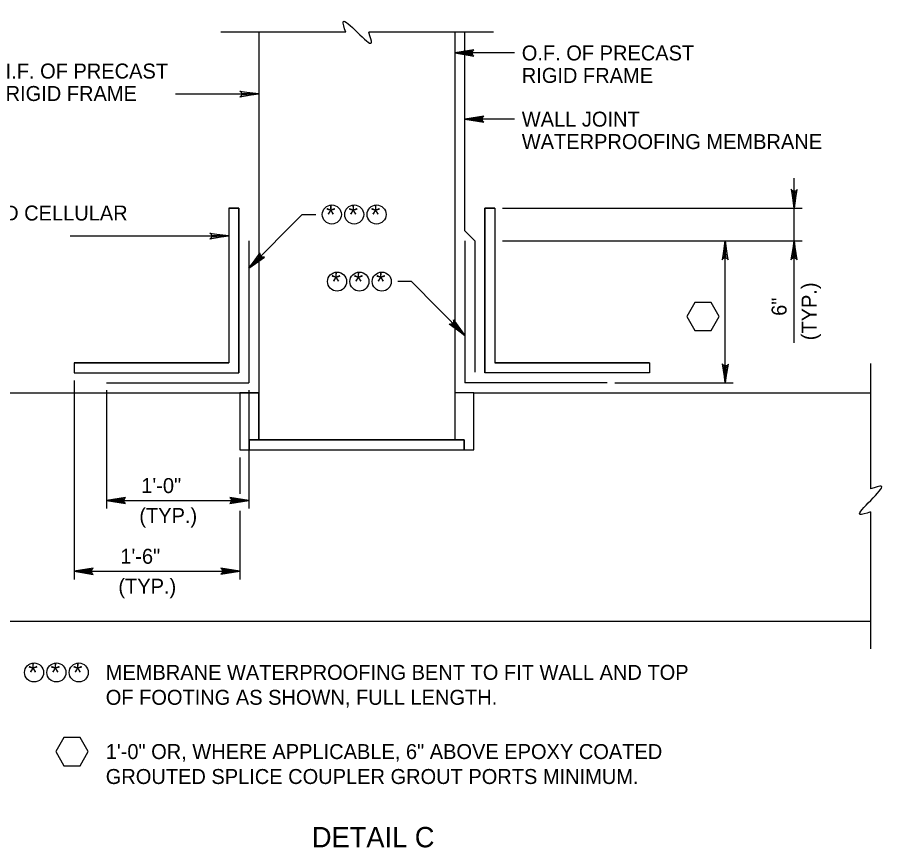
# Model space of a CAD drawing. Extents: x 641328 to 643024, y 298283 to 300065.
# Drawn here: x 641451.7 to 641625.7, y 299059.5 to 299225.9 of the extents above; entities that cross this region are included whole.
import ezdxf

# ---------------------------------------------------------------- set-up
doc = ezdxf.new("R2010")
doc.units = 0
for name, color, linetype in [('2', 7, 'Continuous'), ('Default', 7, 'Continuous'), ('S-TEXT-DIMS-N', 7, 'Continuous')]:
    doc.layers.add(name, color=color, linetype=linetype)

msp = doc.modelspace()

# ---------------------------------------------------------------- linework, layer by layer
at = {"layer": '2'}
for p, q in [((641517.5, 299222.9), (641492.5, 299222.9)), ((641500.08, 299222.9), (641500.08, 299141.21)), ((641547.13, 299222.9), (641522.13, 299222.9)), ((641539.36, 299222.9), (641539.36, 299141.21)), ((641541.36, 299183.14), (641541.36, 299222.9)), ((641543.16, 299219.37), (641539.36, 299218.78)), ((641539.36, 299218.78), (641542.97, 299219.21)), ((641542.83, 299218.95), (641539.36, 299218.78)), ((641539.36, 299218.78), (641542.83, 299218.58)), ((641542.96, 299218.32), (641539.36, 299218.78)), ((641539.36, 299218.78), (641543.15, 299218.15)), ((641539.36, 299218.78), (641542.83, 299218.77)), ((641551.33, 299218.78), (641539.36, 299218.78)), ((641542.97, 299219.21), (641542.83, 299218.95)), ((641542.83, 299218.95), (641542.83, 299218.58)), ((641542.83, 299218.58), (641542.96, 299218.32)), ((641543.15, 299218.15), (641542.96, 299218.32)), ((641542.97, 299219.21), (641543.16, 299219.37)), ((641483.37, 299210.54), (641500.08, 299210.54)), ((641496.47, 299210.97), (641496.28, 299211.13)), ((641496.28, 299211.13), (641500.08, 299210.54)), ((641500.08, 299210.54), (641496.28, 299209.9)), ((641496.28, 299209.9), (641496.48, 299210.08)), ((641496.47, 299210.97), (641496.61, 299210.7)), ((641500.08, 299210.54), (641496.47, 299210.97)), ((641496.48, 299210.08), (641500.08, 299210.54)), ((641496.61, 299210.34), (641496.48, 299210.08)), ((641496.61, 299210.7), (641500.08, 299210.54)), ((641496.61, 299210.7), (641496.61, 299210.34)), ((641500.08, 299210.54), (641496.61, 299210.34)), ((641500.08, 299210.54), (641496.61, 299210.52)), ((641545.16, 299206.1), (641541.36, 299205.51)), ((641544.97, 299205.94), (641545.16, 299206.1)), ((641541.36, 299205.51), (641544.97, 299205.94)), ((641544.83, 299205.68), (641541.36, 299205.51)), ((641541.36, 299205.51), (641544.83, 299205.32)), ((641544.96, 299205.06), (641541.36, 299205.51)), ((641541.36, 299205.51), (641545.15, 299204.88)), ((641541.36, 299205.51), (641544.83, 299205.5)), ((641551.33, 299205.51), (641541.36, 299205.51)), ((641544.97, 299205.94), (641544.83, 299205.68)), ((641544.83, 299205.68), (641544.83, 299205.32)), ((641544.83, 299205.32), (641544.96, 299205.06)), ((641545.15, 299204.88), (641544.96, 299205.06)), ((641607.34, 299160.65), (641607.34, 299193.65)), ((641606.91, 299191.25), (641606.75, 299191.44)), ((641606.75, 299191.44), (641607.34, 299187.64)), ((641606.91, 299191.25), (641607.18, 299191.11)), ((641607.34, 299187.64), (641606.91, 299191.25)), ((641607.18, 299191.11), (641607.34, 299187.64)), ((641607.18, 299191.11), (641607.54, 299191.11)), ((641607.34, 299187.64), (641607.98, 299191.43)), ((641607.8, 299191.23), (641607.34, 299187.64)), ((641607.34, 299187.64), (641607.54, 299191.11)), ((641607.34, 299187.64), (641607.36, 299191.11)), ((641607.54, 299191.11), (641607.8, 299191.23)), ((641607.98, 299191.43), (641607.8, 299191.23)), ((641494.08, 299187.64), (641494.08, 299156.64)), ((641494.08, 299187.64), (641496.08, 299187.64)), ((641494.08, 299187.64), (641494.08, 299156.64)), ((641496.08, 299187.64), (641494.08, 299187.64)), ((641496.08, 299187.64), (641496.08, 299154.64)), ((641496.08, 299154.64), (641496.08, 299187.64)), ((641545.36, 299187.64), (641545.36, 299154.64)), ((641547.36, 299187.64), (641545.36, 299187.64)), ((641545.36, 299154.64), (641545.36, 299187.64)), ((641545.36, 299187.64), (641547.36, 299187.64)), ((641547.36, 299187.64), (641547.36, 299156.64)), ((641547.36, 299187.64), (641547.36, 299156.64)), ((641548.9, 299187.64), (641608.97, 299187.64)), ((641498.08, 299175.61), (641508.77, 299186.39)), ((641508.77, 299186.39), (641511.49, 299186.39)), ((641462.27, 299182.09), (641494.08, 299182.09)), ((641490.47, 299182.52), (641490.28, 299182.68)), ((641490.28, 299182.68), (641494.08, 299182.09)), ((641494.08, 299182.09), (641490.28, 299181.45)), ((641490.28, 299181.45), (641490.48, 299181.63)), ((641490.47, 299182.52), (641490.61, 299182.25)), ((641494.08, 299182.09), (641490.47, 299182.52)), ((641490.48, 299181.63), (641494.08, 299182.09)), ((641490.61, 299181.89), (641490.48, 299181.63)), ((641490.61, 299182.25), (641494.08, 299182.09)), ((641490.61, 299182.25), (641490.61, 299181.89)), ((641494.08, 299182.09), (641490.61, 299181.89)), ((641494.08, 299182.09), (641490.61, 299182.07)), ((641543.36, 299181.14), (641541.36, 299183.14)), ((641498.08, 299181.14), (641498.08, 299152.64)), ((641541.36, 299181.14), (641541.36, 299152.64)), ((641543.36, 299181.14), (641543.36, 299154.82)), ((641548.9, 299181.14), (641608.97, 299181.14)), ((641593.54, 299181.14), (641592.9, 299177.34)), ((641593.08, 299177.54), (641593.54, 299181.14)), ((641593.54, 299181.14), (641593.34, 299177.67)), ((641593.54, 299181.14), (641593.52, 299177.66)), ((641593.7, 299177.66), (641593.54, 299181.14)), ((641593.54, 299181.14), (641593.97, 299177.53)), ((641594.13, 299177.33), (641593.54, 299181.14)), ((641607.34, 299181.14), (641606.71, 299177.34)), ((641606.89, 299177.54), (641607.34, 299181.14)), ((641607.34, 299181.14), (641607.15, 299177.67)), ((641607.34, 299181.14), (641607.33, 299177.66)), ((641607.51, 299177.66), (641607.34, 299181.14)), ((641607.34, 299181.14), (641607.77, 299177.53)), ((641607.93, 299177.33), (641607.34, 299181.14)), ((641500.32, 299178.73), (641498.08, 299175.61)), ((641498.08, 299175.61), (641500.3, 299178.48)), ((641500.4, 299178.2), (641498.08, 299175.61)), ((641500.3, 299178.48), (641500.32, 299178.73)), ((641500.3, 299178.48), (641500.4, 299178.2)), ((641500.4, 299178.2), (641500.65, 299177.95)), ((641593.54, 299152.64), (641593.54, 299179.33)), ((641498.08, 299175.61), (641500.52, 299178.07)), ((641498.08, 299175.61), (641500.65, 299177.95)), ((641498.08, 299175.61), (641501.19, 299177.87)), ((641500.93, 299177.85), (641498.08, 299175.61)), ((641500.65, 299177.95), (641500.93, 299177.85)), ((641501.19, 299177.87), (641500.93, 299177.85)), ((641592.9, 299177.34), (641593.08, 299177.54)), ((641593.34, 299177.67), (641593.08, 299177.54)), ((641593.7, 299177.66), (641593.34, 299177.67)), ((641593.97, 299177.53), (641593.7, 299177.66)), ((641593.97, 299177.53), (641594.13, 299177.33)), ((641606.71, 299177.34), (641606.89, 299177.54)), ((641607.15, 299177.67), (641606.89, 299177.54)), ((641607.51, 299177.66), (641607.15, 299177.67)), ((641607.77, 299177.53), (641607.51, 299177.66)), ((641607.77, 299177.53), (641607.93, 299177.33)), ((641530.66, 299172.95), (641527.95, 299172.95)), ((641541.36, 299162.17), (641530.66, 299172.95)), ((641541.36, 299162.17), (641538.25, 299164.43)), ((641538.25, 299164.43), (641538.51, 299164.42)), ((641538.78, 299164.51), (641538.51, 299164.42)), ((641538.51, 299164.42), (641541.36, 299162.17)), ((641539.04, 299164.76), (641538.78, 299164.51)), ((641541.36, 299162.17), (641538.78, 299164.51)), ((641541.36, 299162.17), (641538.91, 299164.64)), ((641539.13, 299165.05), (641539.04, 299164.76)), ((641539.04, 299164.76), (641541.36, 299162.17)), ((641539.13, 299165.05), (641539.11, 299165.3)), ((641539.11, 299165.3), (641541.36, 299162.17)), ((641541.36, 299162.17), (641539.13, 299165.05)), ((641463.08, 299156.64), (641494.08, 299156.64)), ((641463.08, 299156.64), (641463.08, 299154.64)), ((641494.08, 299156.64), (641463.08, 299156.64)), ((641463.08, 299156.64), (641463.08, 299154.64)), ((641578.36, 299156.64), (641547.36, 299156.64)), ((641547.36, 299156.64), (641578.36, 299156.64)), ((641578.36, 299156.64), (641578.36, 299154.64)), ((641578.36, 299156.64), (641578.36, 299154.64)), ((641593.11, 299156.25), (641592.95, 299156.44)), ((641592.95, 299156.44), (641593.54, 299152.64)), ((641593.11, 299156.25), (641593.37, 299156.11)), ((641593.54, 299152.64), (641593.11, 299156.25)), ((641593.37, 299156.11), (641593.54, 299152.64)), ((641593.37, 299156.11), (641593.73, 299156.11)), ((641593.54, 299152.64), (641594.17, 299156.43)), ((641594, 299156.23), (641593.54, 299152.64)), ((641593.54, 299152.64), (641593.73, 299156.11)), ((641593.54, 299152.64), (641593.55, 299156.11)), ((641593.73, 299156.11), (641594, 299156.23)), ((641594.17, 299156.43), (641594, 299156.23)), ((641622.69, 299156.54), (641622.69, 299131.42)), ((641463.08, 299154.64), (641496.08, 299154.64)), ((641463.08, 299154.64), (641496.08, 299154.64)), ((641578.36, 299154.64), (641545.36, 299154.64)), ((641578.36, 299154.64), (641545.36, 299154.64)), ((641463.08, 299153.1), (641463.08, 299113.28)), ((641469.58, 299152.64), (641498.08, 299152.64)), ((641569.86, 299152.64), (641541.36, 299152.64)), ((641571.4, 299152.64), (641595.16, 299152.64)), ((641469.58, 299151.22), (641469.58, 299127.45)), ((641496.27, 299150.64), (641500.08, 299150.64)), ((641500.08, 299150.64), (641496.27, 299150.64)), ((641498.08, 299151.22), (641498.08, 299127.45)), ((641500.08, 299141.21), (641500.08, 299150.64)), ((641543.17, 299150.64), (641539.36, 299150.64)), ((641543.17, 299150.64), (641539.36, 299150.64)), ((641539.36, 299150.64), (641539.36, 299141.21)), ((641500.08, 299141.21), (641539.36, 299141.21)), ((641539.36, 299141.21), (641541.26, 299141.21)), ((641541.26, 299141.21), (641541.26, 299139.21)), ((641496.27, 299137.68), (641496.27, 299130.43)), ((641473.38, 299129.67), (641469.58, 299129.08)), ((641469.58, 299129.08), (641473.19, 299129.51)), ((641473.19, 299129.51), (641473.05, 299129.25)), ((641473.19, 299129.51), (641473.38, 299129.67)), ((641498.08, 299129.08), (641494.28, 299129.71)), ((641494.28, 299129.71), (641494.48, 299129.54)), ((641494.61, 299129.28), (641494.48, 299129.54)), ((641494.48, 299129.54), (641498.08, 299129.08)), ((641473.05, 299129.25), (641469.58, 299129.08)), ((641469.58, 299129.08), (641496.27, 299129.08)), ((641469.58, 299129.08), (641473.05, 299128.88)), ((641473.18, 299128.62), (641469.58, 299129.08)), ((641469.58, 299129.08), (641473.37, 299128.45)), ((641469.58, 299129.08), (641473.05, 299129.06)), ((641473.05, 299129.25), (641473.05, 299128.88)), ((641473.05, 299128.88), (641473.18, 299128.62)), ((641473.37, 299128.45), (641473.18, 299128.62)), ((641494.28, 299128.49), (641498.08, 299129.08)), ((641494.47, 299128.65), (641494.28, 299128.49)), ((641498.08, 299129.08), (641494.47, 299128.65)), ((641494.47, 299128.65), (641494.61, 299128.91)), ((641498.08, 299129.08), (641494.61, 299129.28)), ((641494.61, 299128.91), (641494.61, 299129.28)), ((641498.08, 299129.08), (641494.61, 299129.09)), ((641494.61, 299128.91), (641498.08, 299129.08)), ((641496.27, 299126.99), (641496.27, 299113.28)), ((641622.69, 299126.79), (641622.69, 299099.38)), ((641466.88, 299115.49), (641463.08, 299114.9)), ((641466.69, 299115.33), (641466.88, 299115.49)), ((641496.27, 299114.9), (641492.47, 299115.54)), ((641492.47, 299115.54), (641492.67, 299115.36)), ((641463.08, 299114.9), (641466.69, 299115.33)), ((641466.55, 299115.07), (641463.08, 299114.9)), ((641463.08, 299114.9), (641496.27, 299114.9)), ((641463.08, 299114.9), (641466.55, 299114.71)), ((641466.68, 299114.44), (641463.08, 299114.9)), ((641463.08, 299114.9), (641466.87, 299114.27)), ((641463.08, 299114.9), (641466.55, 299114.89)), ((641466.69, 299115.33), (641466.55, 299115.07)), ((641466.55, 299115.07), (641466.55, 299114.71)), ((641466.55, 299114.71), (641466.68, 299114.44)), ((641466.87, 299114.27), (641466.68, 299114.44)), ((641492.47, 299114.31), (641496.27, 299114.9)), ((641492.66, 299114.47), (641492.47, 299114.31)), ((641496.27, 299114.9), (641492.66, 299114.47)), ((641492.66, 299114.47), (641492.8, 299114.74)), ((641492.8, 299115.1), (641492.67, 299115.36)), ((641492.67, 299115.36), (641496.27, 299114.9)), ((641496.27, 299114.9), (641492.8, 299115.1)), ((641492.8, 299114.74), (641492.8, 299115.1)), ((641496.27, 299114.9), (641492.8, 299114.92)), ((641492.8, 299114.74), (641496.27, 299114.9)), ((641442.93, 299104.92), (641622.69, 299104.92))]:
    msp.add_line(p, q, dxfattribs=at)
for points in [[(641442.93, 299150.64), (641496.27, 299150.64), (641496.27, 299139.21), (641543.17, 299139.21), (641543.17, 299150.64), (641622.69, 299150.64)], [(641496.27, 299150.64), (641496.27, 299139.21), (641498.17, 299139.21)], [(641541.26, 299139.21), (641543.17, 299139.21), (641543.17, 299150.64)], [(641498.17, 299139.21), (641498.17, 299141.21), (641500.08, 299141.21)]]:
    msp.add_lwpolyline(points, dxfattribs=at)
msp.add_lwpolyline([(641498.17, 299141.21), (641498.17, 299139.21), (641541.26, 299139.21), (641541.26, 299141.21)], close=True, dxfattribs=at)
for points in [[(641517.5, 299222.9), (641517, 299225.03), (641522.63, 299220.78), (641522.13, 299222.9)], [(641622.69, 299126.79), (641620.57, 299126.29), (641624.82, 299131.92), (641622.69, 299131.42)]]:
    msp.add_spline(points, degree=3, dxfattribs=at)
at = {"layer": 'S-TEXT-DIMS-N'}
for points in [[(641585.84, 299165.98), (641587.46, 299163.17), (641590.71, 299163.17), (641592.33, 299165.98), (641590.71, 299168.79), (641587.46, 299168.79)], [(641459.41, 299078.75), (641461.04, 299075.94), (641464.28, 299075.94), (641465.91, 299078.75), (641464.28, 299081.56), (641461.04, 299081.56)]]:
    msp.add_lwpolyline(points, close=True, dxfattribs=at)
for centre in [(641514.72, 299186.39), (641519.2, 299186.39), (641523.68, 299186.39), (641515.76, 299172.95), (641520.24, 299172.95), (641524.72, 299172.95), (641455.04, 299094.62), (641459.52, 299094.62), (641464, 299094.62)]:
    msp.add_circle(centre, 1.91, dxfattribs=at)

# ---------------------------------------------------------------- texts
at = {"layer": '2'}
for s, p in [('O.F. OF PRECAST ', (641552.78, 299217.26)), ('I.F. OF PRECAST ', (641449.35, 299213.64)), ('RIGID FRAME', (641552.78, 299212.76)), ('RIGID FRAME', (641449.35, 299209.14)), ('WALL JOINT', (641552.78, 299204)), ('WATERPROOFING MEMBRANE', (641552.78, 299199.5)), ('1" THICK PREFORMED CELLULAR ', (641408.4, 299185.19)), ('1\'-0"', (641476.53, 299130.57)), ('(TYP.)', (641476.14, 299124.57)), ('1\'-6"', (641472.33, 299116.4)), ('(TYP.)', (641471.94, 299110.4)), ('MEMBRANE WATERPROOFING BENT TO FIT WALL AND TOP ', (641469.41, 299093.14)), ('OF FOOTING AS SHOWN, FULL LENGTH.', (641469.41, 299088.14)), ('1\'-0" OR, WHERE APPLICABLE, 6" ABOVE EPOXY COATED ', (641469.41, 299077.27)), ('GROUTED SPLICE COUPLER GROUT PORTS MINIMUM. ', (641469.41, 299072.27))]:
    msp.add_text(s, height=3, dxfattribs=at).set_placement(p)
for s, p in [('(TYP.)', (641611.84, 299161.19)), ('6"', (641605.84, 299166.08))]:
    msp.add_text(s, height=3, rotation=90, dxfattribs=at).set_placement(p)
at = {"layer": 'Default'}
msp.add_text('DETAIL C', height=4.08, dxfattribs=at).set_placement((641510.72, 299059.58))
at = {"layer": 'S-TEXT-DIMS-N'}
for p in [(641513.56, 299184.56), (641518.05, 299184.56), (641522.53, 299184.56), (641514.61, 299171.13), (641519.09, 299171.13), (641523.57, 299171.13), (641453.89, 299092.8), (641458.37, 299092.8), (641462.85, 299092.8)]:
    msp.add_text('*', height=3.65, dxfattribs=at).set_placement(p)

doc.saveas('drawing.dxf')
